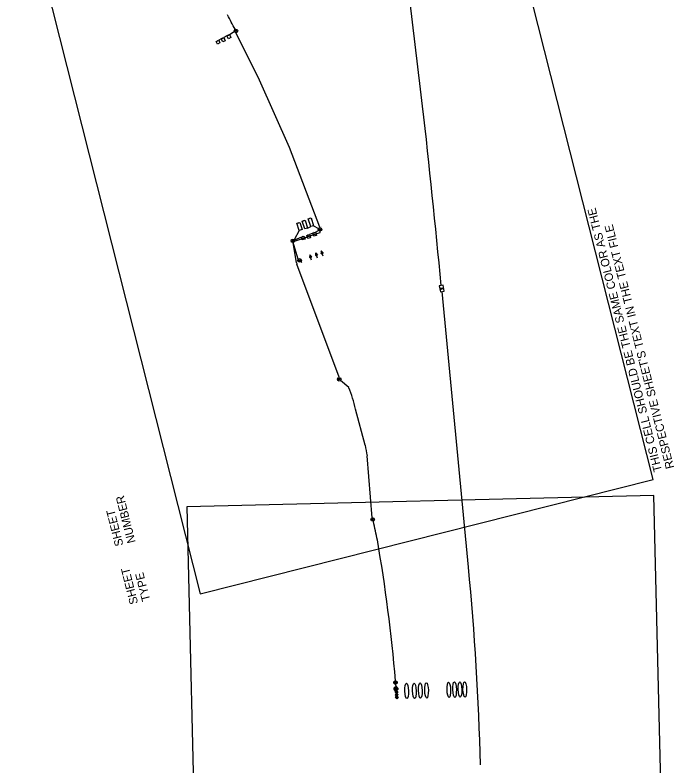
# Model space of a CAD drawing. Extents: x 601462 to 605493, y 331960 to 402715.
# Drawn here: x 603461 to 604836, y 347935 to 349499 of the extents above; entities that cross this region are included whole.
import ezdxf

# ---------------------------------------------------------------- set-up
doc = ezdxf.new("R2010")
doc.units = 0
for name, color, linetype in [('Default', 7, 'Continuous'), ('P_FTMS', 7, 'Continuous'), ('P_FTMSConduit', 7, 'Continuous'), ('P_MISC_TXT_2A (Construction)', 7, 'Continuous'), ('P_MISC_TXT_2B (Construction)', 7, 'Continuous')]:
    doc.layers.add(name, color=color, linetype=linetype)

# ---------------------------------------------------------------- blocks, each defined once
blk = doc.blocks.new('POINT_DISPLAY')
at = {"layer": 'Default'}
blk.add_line((0, 0), (0, 0), dxfattribs=at)
blk = doc.blocks.new('_U228')
at = {"layer": 'P_FTMS'}
for p, q in [((-4.5, 3.2), (1.5, -0.2)), ((-4.4, 2.8), (1.3, -0.4)), ((-4.3, 3.5), (1.8, 0)), ((-3.9, 3.4), (-4.3, 2.6)), ((-4.3, 2.4), (1, -0.6)), ((-3.5, 3.4), (-4.2, 2.2)), ((-4.2, 2), (0.7, -0.8)), ((-3.2, 3.3), (-4.1, 1.7)), ((-4.1, 1.6), (0.5, -1)), ((-2.9, 3.3), (-4, 1.3)), ((-4, 1.2), (0.2, -1.2)), ((-2.6, 3.2), (-3.9, 0.9)), ((-2.2, 3.2), (-3.8, 0.5)), ((-3.8, 0.7), (0, -1.4)), ((-1.9, 3.2), (-3.7, 0.1)), ((-3.7, 0.3), (-0.3, -1.6)), ((-3.5, 3.4), (2, 0.2)), ((-1.6, 3.1), (-3.5, -0.3)), ((-1.3, 3.1), (-3.4, -0.7)), ((-0.9, 3), (-3.3, -1.2)), ((-0.6, 3), (-3.2, -1.6)), ((-0.3, 2.9), (-3.1, -2)), ((0, 2.9), (-3, -2.4)), ((0.4, 2.8), (-2.9, -2.8)), ((-2.7, 3.3), (2.3, 0.4)), ((0.7, 2.8), (-2.7, -3.2)), ((1, 2.8), (-2.5, -3.4)), ((-1.9, 3.2), (2.5, 0.6)), ((1.3, 2.7), (-1.8, -2.9)), ((1.7, 2.7), (-1.2, -2.3)), ((-1.1, 3), (2.8, 0.8)), ((2, 2.6), (-0.5, -1.8)), ((-0.3, 2.9), (3.1, 1)), ((2.3, 2.6), (0.1, -1.3)), ((0.5, 2.8), (3.3, 1.2)), ((2.6, 2.5), (0.7, -0.8)), ((1.3, 2.7), (3.6, 1.4)), ((3, 2.5), (1.4, -0.3)), ((3.3, 2.4), (2, 0.2)), ((2.2, 2.6), (3.8, 1.6)), ((3.6, 2.4), (2.7, 0.7)), ((3, 2.5), (4.1, 1.8)), ((3.9, 2.3), (3.3, 1.2)), ((3.8, 2.4), (4.3, 2.1)), ((4.3, 2.3), (4, 1.7)), ((-3.6, -0.1), (-0.5, -1.8)), ((-3.5, -0.5), (-0.8, -2)), ((-3.4, -0.9), (-1.1, -2.2)), ((-3.3, -1.3), (-1.3, -2.4)), ((-3.2, -1.7), (-1.6, -2.7)), ((-3, -2.2), (-1.8, -2.9)), ((-2.9, -2.6), (-2.1, -3.1)), ((-2.8, -3), (-2.3, -3.3)), ((-2.7, -3.4), (-2.6, -3.5))]:
    blk.add_line(p, q, dxfattribs=at)
blk.add_lwpolyline([(-4.6, 3.5), (4.6, 2.3), (-2.7, -3.5)], close=True, dxfattribs=at)
blk.add_blockref('POINT_DISPLAY', (4.6, 2.3), dxfattribs=at)
blk = doc.blocks.new('_U229')
at = {"layer": 'P_FTMS'}
for p, q in [((-4.5, 3.2), (1.5, -0.2)), ((-4.4, 2.8), (1.3, -0.4)), ((-4.3, 3.5), (1.8, 0)), ((-3.9, 3.4), (-4.3, 2.6)), ((-4.3, 2.4), (1, -0.6)), ((-3.5, 3.4), (-4.2, 2.2)), ((-4.2, 2), (0.7, -0.8)), ((-3.2, 3.3), (-4.1, 1.7)), ((-4.1, 1.6), (0.5, -1)), ((-2.9, 3.3), (-4, 1.3)), ((-4, 1.2), (0.2, -1.2)), ((-2.6, 3.2), (-3.9, 0.9)), ((-2.2, 3.2), (-3.8, 0.5)), ((-3.8, 0.7), (0, -1.4)), ((-1.9, 3.2), (-3.7, 0.1)), ((-3.7, 0.3), (-0.3, -1.6)), ((-3.5, 3.4), (2, 0.2)), ((-1.6, 3.1), (-3.5, -0.3)), ((-1.3, 3.1), (-3.4, -0.7)), ((-0.9, 3), (-3.3, -1.2)), ((-0.6, 3), (-3.2, -1.6)), ((-0.3, 2.9), (-3.1, -2)), ((0, 2.9), (-3, -2.4)), ((0.4, 2.8), (-2.9, -2.8)), ((-2.7, 3.3), (2.3, 0.4)), ((0.7, 2.8), (-2.7, -3.2)), ((1, 2.8), (-2.5, -3.4)), ((-1.9, 3.2), (2.5, 0.6)), ((1.3, 2.7), (-1.8, -2.9)), ((1.7, 2.7), (-1.2, -2.3)), ((-1.1, 3), (2.8, 0.8)), ((2, 2.6), (-0.5, -1.8)), ((-0.3, 2.9), (3.1, 1)), ((2.3, 2.6), (0.1, -1.3)), ((0.5, 2.8), (3.3, 1.2)), ((2.6, 2.5), (0.7, -0.8)), ((1.3, 2.7), (3.6, 1.4)), ((3, 2.5), (1.4, -0.3)), ((3.3, 2.4), (2, 0.2)), ((2.2, 2.6), (3.8, 1.6)), ((3.6, 2.4), (2.7, 0.7)), ((3, 2.5), (4.1, 1.8)), ((3.9, 2.3), (3.3, 1.2)), ((3.8, 2.4), (4.3, 2.1)), ((4.3, 2.3), (4, 1.7)), ((-3.6, -0.1), (-0.5, -1.8)), ((-3.5, -0.5), (-0.8, -2)), ((-3.4, -0.9), (-1.1, -2.2)), ((-3.3, -1.3), (-1.3, -2.4)), ((-3.2, -1.7), (-1.6, -2.7)), ((-3, -2.2), (-1.8, -2.9)), ((-2.9, -2.6), (-2.1, -3.1)), ((-2.8, -3), (-2.3, -3.3)), ((-2.7, -3.4), (-2.6, -3.5))]:
    blk.add_line(p, q, dxfattribs=at)
blk.add_lwpolyline([(-4.6, 3.5), (4.6, 2.3), (-2.7, -3.5)], close=True, dxfattribs=at)
blk.add_blockref('POINT_DISPLAY', (4.6, 2.3), dxfattribs=at)
blk = doc.blocks.new('_U230')
at = {"layer": 'P_FTMS'}
for p, q in [((12.1, 1.6), (-12.2, -0.1)), ((11.8, 3), (-12.1, 1.4)), ((11.9, 2.3), (-12.1, 0.6)), ((12.1, 0.8), (-12.1, -0.8)), ((12.1, 0.1), (-12.1, -1.6)), ((11.6, 3.7), (-12, 2.1)), ((-11.9, 2.5), (-11.4, -4.2)), ((11.3, 4.4), (-11.8, 2.9)), ((11, 5.2), (-11.6, 3.6)), ((10.6, 5.9), (-11.4, 4.4)), ((-11.3, 4.5), (-10.6, -6)), ((10.2, 6.6), (-11, 5.1)), ((9.8, 7.3), (-10.7, 5.9)), ((-10.7, 5.9), (-9.8, -7.2)), ((9.2, 8), (-10.2, 6.6)), ((-10, 6.9), (-9, -8.2)), ((8.6, 8.6), (-9.7, 7.4)), ((-9.3, 7.8), (-8.2, -9)), ((7.8, 9.3), (-9, 8.2)), ((-8.6, 8.5), (-7.4, -9.6)), ((6.9, 10), (-8.2, 9)), ((-8, 9.2), (-6.6, -10.2)), ((-7.3, 9.7), (-5.9, -10.6)), ((5.8, 10.7), (-7.2, 9.8)), ((-6.6, 10.3), (-5.1, -11)), ((4.5, 11.3), (-6, 10.6)), ((-5.9, 10.7), (-4.4, -11.4)), ((-5.1, 11), (-3.6, -11.6)), ((-4.4, 11.3), (-2.9, -11.8)), ((2.5, 11.9), (-4.1, 11.5)), ((-3.7, 11.6), (-2.1, -12)), ((-3, 11.8), (-1.4, -12.1)), ((-2.3, 12), (-0.6, -12.2)), ((-1.6, 12.1), (0.1, -12.2)), ((-0.8, 12.1), (0.8, -12.1)), ((-0.1, 12.2), (1.6, -12.1)), ((0.6, 12.1), (2.3, -11.9)), ((1.4, 12.1), (3, -11.8)), ((2.1, 12), (3.7, -11.6)), ((2.9, 11.8), (4.4, -11.3)), ((3.6, 11.6), (5.1, -11)), ((4.4, 11.3), (5.9, -10.7)), ((5.1, 11), (6.6, -10.2)), ((5.9, 10.6), (7.3, -9.8)), ((6.6, 10.2), (8, -9.2)), ((7.4, 9.7), (8.6, -8.6)), ((8.2, 9), (9.3, -7.8)), ((9, 8.2), (10, -6.9)), ((9.8, 7.2), (10.7, -5.8)), ((10.6, 5.9), (11.3, -4.5)), ((11.5, 4), (11.9, -2.5)), ((12.1, -0.6), (-12, -2.3)), ((12.1, -1.4), (-11.8, -3)), ((12, -2.1), (-11.6, -3.7)), ((11.8, -2.9), (-11.3, -4.4)), ((11.6, -3.6), (-11, -5.1)), ((11.3, -4.4), (-10.7, -5.9)), ((11.1, -5.1), (-10.2, -6.6)), ((10.6, -5.9), (-9.8, -7.3)), ((10.2, -6.6), (-9.2, -8)), ((9.6, -7.4), (-8.5, -8.6)), ((9, -8.2), (-7.8, -9.3)), ((8.2, -9), (-6.9, -10)), ((7.3, -9.8), (-5.8, -10.7)), ((6, -10.6), (-4.5, -11.3)), ((4.1, -11.5), (-2.6, -11.9))]:
    blk.add_line(p, q, dxfattribs=at)
blk.add_circle((0, 0), 12.2, dxfattribs=at)
blk = doc.blocks.new('FMD')
at = {"layer": 'P_FTMS'}
for p, q in [((16.9, 17.6), (-16.9, 17.6)), ((-16.1, 16.1), (-16.1, 18.4)), ((16.1, 16.1), (-16.1, 16.1)), ((15.5, 19), (-15.5, 19)), ((-14.6, 14.6), (-14.6, 19.9)), ((14.6, 14.6), (-14.6, 14.6)), ((14, 20.5), (-14, 20.5)), ((-13.2, 13.2), (-13.2, 21.3)), ((13.2, 13.2), (-13.2, 13.2)), ((12.5, 21.9), (-12.5, 21.9)), ((-11.7, 11.7), (-11.7, 22.8)), ((11.7, 11.7), (-11.7, 11.7)), ((11.1, 23.4), (-11.1, 23.4)), ((-10.2, 10.2), (-10.2, 24.2)), ((10.2, 10.2), (-10.2, 10.2)), ((9.6, 24.9), (-9.6, 24.9)), ((-8.8, 8.8), (-8.8, 25.7)), ((8.8, 8.8), (-8.8, 8.8)), ((8.2, 26.3), (-8.2, 26.3)), ((-7.3, 7.3), (-7.3, 27.2)), ((7.3, 7.3), (-7.3, 7.3)), ((6.7, 27.8), (-6.7, 27.8)), ((-5.9, 5.9), (-5.9, 28.6)), ((5.9, 5.9), (-5.9, 5.9)), ((5.2, 29.3), (-5.2, 29.3)), ((-4.4, 4.4), (-4.4, 30.1)), ((4.4, 4.4), (-4.4, 4.4)), ((3.8, 30.7), (-3.8, 30.7)), ((-2.9, 2.9), (-2.9, 31.6)), ((2.9, 2.9), (-2.9, 2.9)), ((2.3, 32.2), (-2.3, 32.2)), ((-1.5, 1.5), (-1.5, 33)), ((1.5, 1.5), (-1.5, 1.5)), ((0.8, 33.6), (-0.8, 33.6)), ((0, 0), (0, 34.5)), ((1.5, 1.5), (1.5, 33)), ((2.9, 2.9), (2.9, 31.6)), ((4.4, 4.4), (4.4, 30.1)), ((5.9, 5.9), (5.9, 28.6)), ((7.3, 7.3), (7.3, 27.2)), ((8.8, 8.8), (8.8, 25.7)), ((10.2, 10.2), (10.2, 24.2)), ((11.7, 11.7), (11.7, 22.8)), ((13.2, 13.2), (13.2, 21.3)), ((14.6, 14.6), (14.6, 19.9)), ((16.1, 16.1), (16.1, 18.4))]:
    blk.add_line(p, q, dxfattribs=at)
blk.add_lwpolyline([(-17.2, 17.2), (0, 34.5), (17.2, 17.2), (0, 0)], close=True, dxfattribs=at)
blk = doc.blocks.new('FTMS_FCV')
at = {"layer": 'P_FTMS'}
blk.add_line((12.7, 16.3), (0.6, -21.9), dxfattribs=at)
blk.add_lwpolyline([(39.1, 24.4), (-39.1, 24.4), (-39.1, -24.4), (39.1, -24.4)], close=True, dxfattribs=at)
blk.add_lwpolyline([(-12.1, 16.2), (0.6, -21.9)], dxfattribs=at)

msp = doc.modelspace()

# ---------------------------------------------------------------- linework, layer by layer
at = {"layer": 'P_FTMS'}
for p, q in [((603908.5, 349458.7), (603918.1, 349464.9)), ((603891.3, 349449.5), (603886.1, 349446.8)), ((603903.1, 349456), (603896.7, 349452.1)), ((604071.4, 349055), (604078.3, 349058)), ((604084, 349059.9), (604094.3, 349054.2)), ((604054.2, 349049.7), (604043.7, 349030.7)), ((604082.4, 349044.5), (604075.5, 349041.5)), ((604088.1, 349046.3), (604094.6, 349049.8)), ((604058.5, 349035.9), (604044.2, 349029.8)), ((604092.2, 348992.4), (604090.2, 348998.2)), ((604103.7, 348996.1), (604101.8, 349002)), ((604079.8, 348988.2), (604077.8, 348994))]:
    msp.add_line(p, q, dxfattribs=at)
for points in [[(603894.4, 349443.2), (603891.3, 349449.5), (603891.3, 349449.5), (603896.7, 349452.1), (603899.8, 349445.8), (603894.4, 349443.2)], [(603906.2, 349449.7), (603903.1, 349456), (603903.1, 349456), (603908.5, 349458.7), (603911.6, 349452.4), (603906.2, 349449.7)], [(603880.7, 349444.1), (603886.1, 349446.8), (603888.7, 349441.4), (603883.3, 349438.8), (603880.7, 349444.1)], [(604073, 349074.2), (604078.7, 349076), (604084, 349059.9), (604078.3, 349058), (604078.3, 349058), (604073, 349074.2)], [(604049.3, 349065), (604055, 349066.8), (604059.9, 349051.6), (604054.2, 349049.7), (604049.3, 349065)], [(604060.5, 349069.3), (604066.2, 349071.2), (604071.4, 349055), (604065.7, 349053.2), (604065.7, 349053.2), (604060.5, 349069.3)], [(604072, 349033), (604069.8, 349039.6), (604069.8, 349039.6), (604075.5, 349041.5), (604077.7, 349034.8), (604072, 349033)], [(604084.6, 349037.8), (604082.4, 349044.5), (604082.4, 349044.5), (604088.1, 349046.3), (604090.3, 349039.7), (604084.6, 349037.8)], [(604058.5, 349035.9), (604064.2, 349037.7), (604066.1, 349032), (604060.3, 349030.2), (604058.5, 349035.9)]]:
    msp.add_lwpolyline(points, dxfattribs=at)
for centre in [(603922.1, 349466.2), (604097.5, 349052.2), (604040.8, 349028.3), (604054.8, 348987.5), (604137.5, 348739.5), (604207.4, 348446.9), (604255, 348106.9)]:
    msp.add_circle(centre, 3.75, dxfattribs=at)
for centre, start, end in [((603921.6, 349470.7), 222.4831, 328.7387), ((603922.5, 349461.7), 42.4831, 148.7387), ((604097.3, 349056.7), 219.4323, 325.6879), ((604097.7, 349047.7), 39.4323, 145.6879), ((604040.6, 349032.8), 219.4323, 325.6879), ((604041, 349023.9), 39.4323, 145.6879), ((604054.6, 348992), 219.4323, 325.6879), ((604055, 348983), 39.4323, 145.6879), ((604137.1, 348743.9), 222.4831, 328.7387), ((604138, 348735), 42.4831, 148.7387), ((604206.9, 348451.4), 222.4831, 328.7387), ((604207.8, 348442.4), 42.4831, 148.7387), ((604254.6, 348111.3), 222.4831, 328.7387), ((604255.5, 348102.4), 42.4831, 148.7387)]:
    msp.add_arc(centre, 3.75, start, end, dxfattribs=at)
for centre in [(604278.1, 348089.3), (604294.4, 348089.7), (604306.9, 348090.1), (604319.7, 348090.5), (604366.2, 348091.6), (604378.2, 348092), (604389.6, 348092.4), (604399.5, 348092.6)]:
    msp.add_ellipse(centre, major_axis=(-0.5, 16), ratio=0.23471, dxfattribs=at)
at = {"layer": 'P_FTMSConduit'}
for p, q in [((603892.9, 349450.8), (603895.2, 349450.6)), ((603893.4, 349449.8), (603894.6, 349451.7)), ((603904.7, 349457.4), (603907, 349457.2)), ((603905.2, 349456.4), (603906.4, 349458.3)), ((603971.5, 349363.5), (603922.5, 349461.7)), ((603882.5, 349445.6), (603884.7, 349445.4)), ((603883, 349444.6), (603884.2, 349446.5)), ((604033.7, 349223.1), (603971.5, 349363.5)), ((604097.3, 349056.7), (604033.7, 349223.1)), ((604074.5, 349075.3), (604076.7, 349074.8)), ((604074.9, 349074.2), (604076.3, 349075.9)), ((604051, 349066.1), (604053.2, 349065.6)), ((604051.4, 349065), (604052.8, 349066.8)), ((604062, 349070.4), (604064.1, 349069.9)), ((604062.3, 349069.3), (604063.7, 349071)), ((604044.4, 349027.5), (604097.7, 349045.8)), ((604071.9, 349039.7), (604073.4, 349041.4)), ((604084.2, 349045.5), (604086.4, 349044.9)), ((604084.6, 349044.4), (604086, 349046.1)), ((604097.7, 349045.8), (604097.6, 349048.4)), ((604060.5, 349037.1), (604062.7, 349036.6)), ((604060.8, 349036), (604062.3, 349037.7)), ((604071.6, 349040.7), (604073.8, 349040.2)), ((604048.6, 348982.2), (604041.4, 349024.6)), ((604051.7, 348989.7), (604041.4, 349024.6)), ((604137.1, 348743.9), (604049.3, 348979.4)), ((604059.5, 348982.5), (604057.9, 348985.4)), ((604407.2, 348347.3), (604352.4, 348922.7)), ((604256.7, 348097.8), (604255.1, 348102.8))]:
    msp.add_line(p, q, dxfattribs=at)
for points in [[(604157.6, 348722), (604140.4, 348737)], [(604191.5, 348602), (604171.8, 348677.4)], [(604206.3, 348450.7), (604195.7, 348579.8)]]:
    msp.add_lwpolyline(points, dxfattribs=at)
for centre, radius, start, end in [((586818.9, 347308.2), 17606.6, 5.30276, 7.75042), ((600886.7, 347893.6), 3418.4, 27.452, 28.0179), ((604100.1, 349057.8), 0.001, 349.2519, 16.8351), ((604063.3, 348984.7), 15, 189.5498, 200.4471), ((603877.8, 348607.9), 302.1, 13.2898, 22.1702), ((604631.7, 348673.8), 446, 189.2683, 192.171), ((600923.7, 347718.7), 3364.1, 11.7565, 12.4342), ((600891.6, 347826.7), 3375.3, 4.8268, 9.8531), ((598624.1, 347788.6), 5810, 1.4429, 5.51866)]:
    msp.add_arc(centre, radius, start, end, dxfattribs=at)
at = {"layer": 'P_MISC_TXT_2A (Construction)'}
msp.add_lwpolyline([(604831.9, 346922.5), (604794.2, 348497), (603819.5, 348473.7), (603857.2, 346899.1)], close=True, dxfattribs=at)
at = {"layer": 'P_MISC_TXT_2B (Construction)'}
msp.add_lwpolyline([(604792.3, 348530.7), (604406.2, 350057.6), (603461, 349818.6), (603847.1, 348291.7)], close=True, dxfattribs=at)

# ---------------------------------------------------------------- block references
at = {"layer": 'P_FTMS'}
for name, p, xscale, yscale, rotation in [('_U229', (604076.6, 348995.9), 0.6330710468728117, -0.6330710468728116, 123.87368883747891), ('_U228', (604088.9, 349000.1), 0.6330710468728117, -0.6330710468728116, 123.87368883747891), ('_U228', (604100.5, 349003.9), 0.6330710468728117, -0.6330710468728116, 123.87368883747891), ('FTMS_FCV', (604351.3, 348929), 0.1640416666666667, 0.16404166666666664, 100.15149376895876), ('_U230', (604255.9, 348093.9), 0.32808333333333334, 0.3280833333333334, -172.77099164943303), ('FMD', (604259.7, 348087.3), 0.1640416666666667, 0.1640416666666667, 93.12187258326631), ('FMD', (604260, 348081.6), 0.1640416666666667, 0.1640416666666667, 93.12187258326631), ('FMD', (604260.3, 348076.2), 0.1640416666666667, 0.1640416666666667, 93.12187258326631)]:
    msp.add_blockref(name, p, dxfattribs=dict(at, xscale=xscale, yscale=yscale, rotation=rotation))

# ---------------------------------------------------------------- texts
at = {"layer": 'P_MISC_TXT_2B (Construction)'}
for s, p in [('THIS CELL SHOULD BE THE SAME COLOR AS THE', (604811.1, 348548.8)), ("RESPECTIVE SHEET'S TEXT IN THE TEXT FILE", (604836.5, 348555.2)), ('NUMBER', (603712.8, 348400)), ('SHEET', (603687.3, 348393.6)), ('SHEET', (603718, 348272.4)), ('TYPE', (603743.4, 348278.8))]:
    msp.add_text(s, height=17.5, rotation=104.191, dxfattribs=at).set_placement(p)

doc.saveas('drawing.dxf')
